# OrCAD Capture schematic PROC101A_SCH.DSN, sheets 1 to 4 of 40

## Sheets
1 04. BLOCK DIAGRAM_XDS110: title: BLOCK DIAGRAM_XDS110; rev: E2
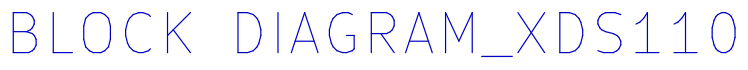
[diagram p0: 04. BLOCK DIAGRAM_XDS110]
2 16. CPSW RGMII_1 ETHERNET PHY: size C; title: CPSW RGMII_1 ETHERNET PHY
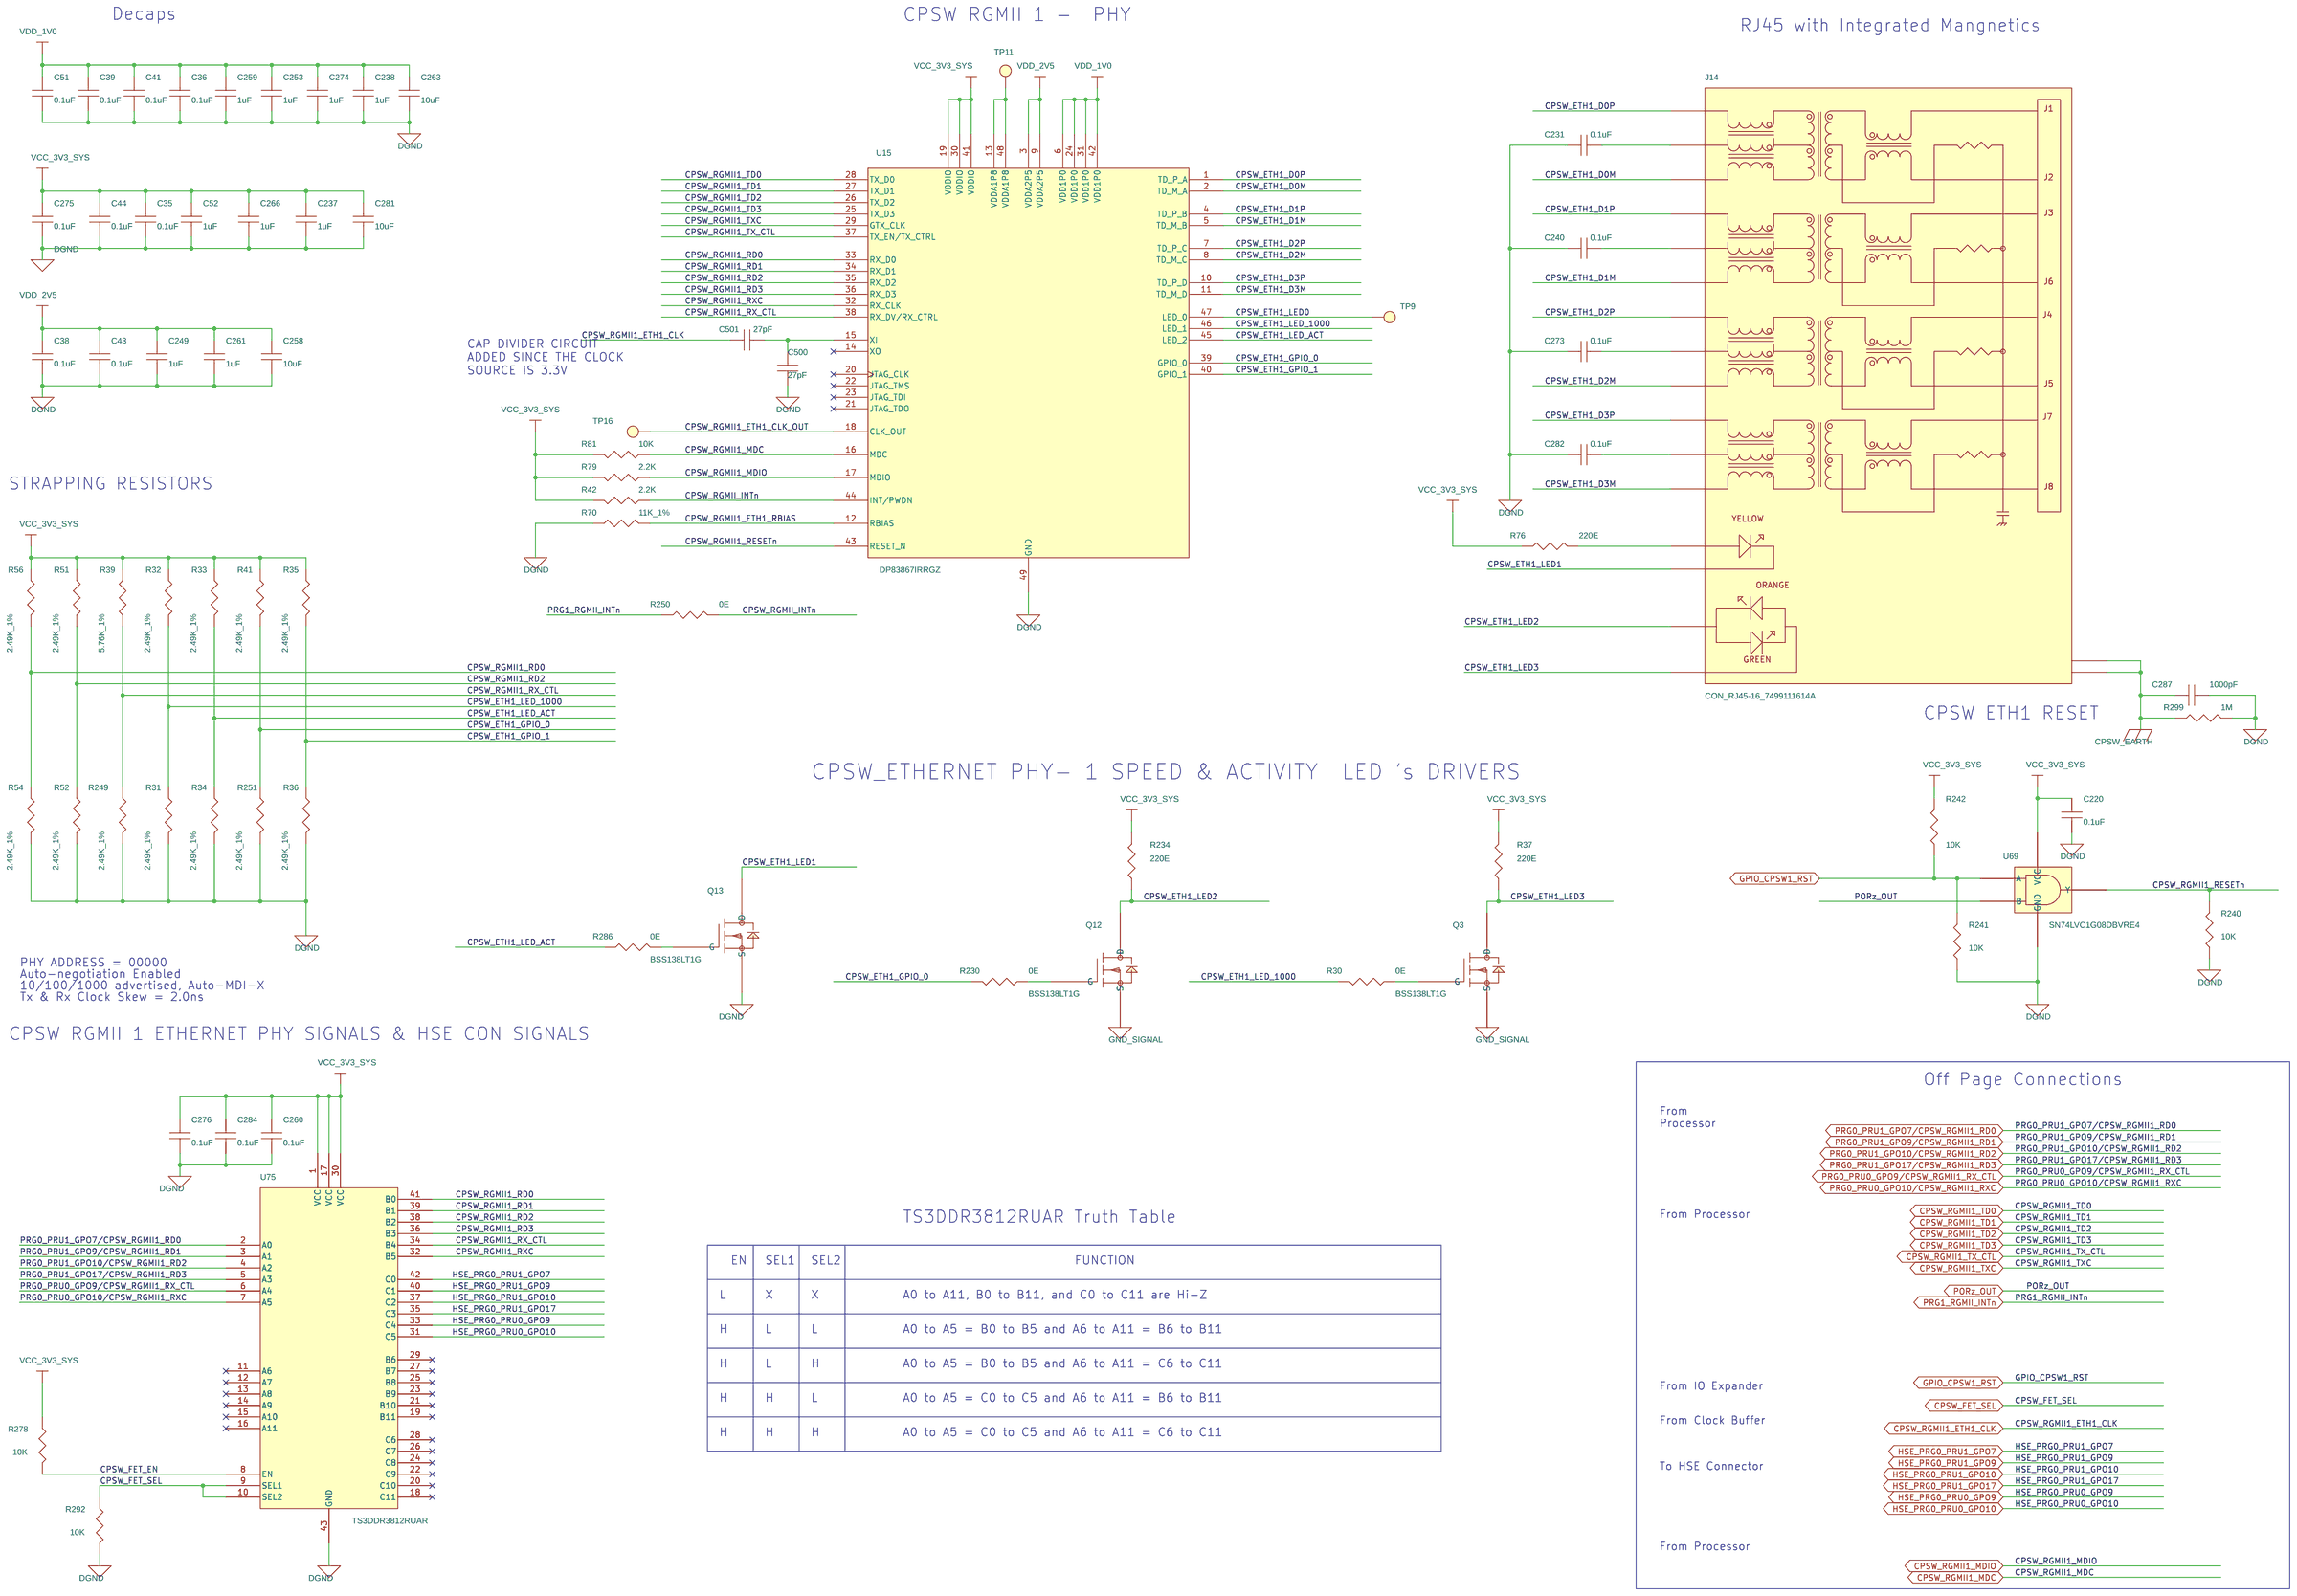
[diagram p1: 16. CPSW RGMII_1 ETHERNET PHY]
3 10.SOC POWER CAPS: size C; title: SOC POWER CAPS
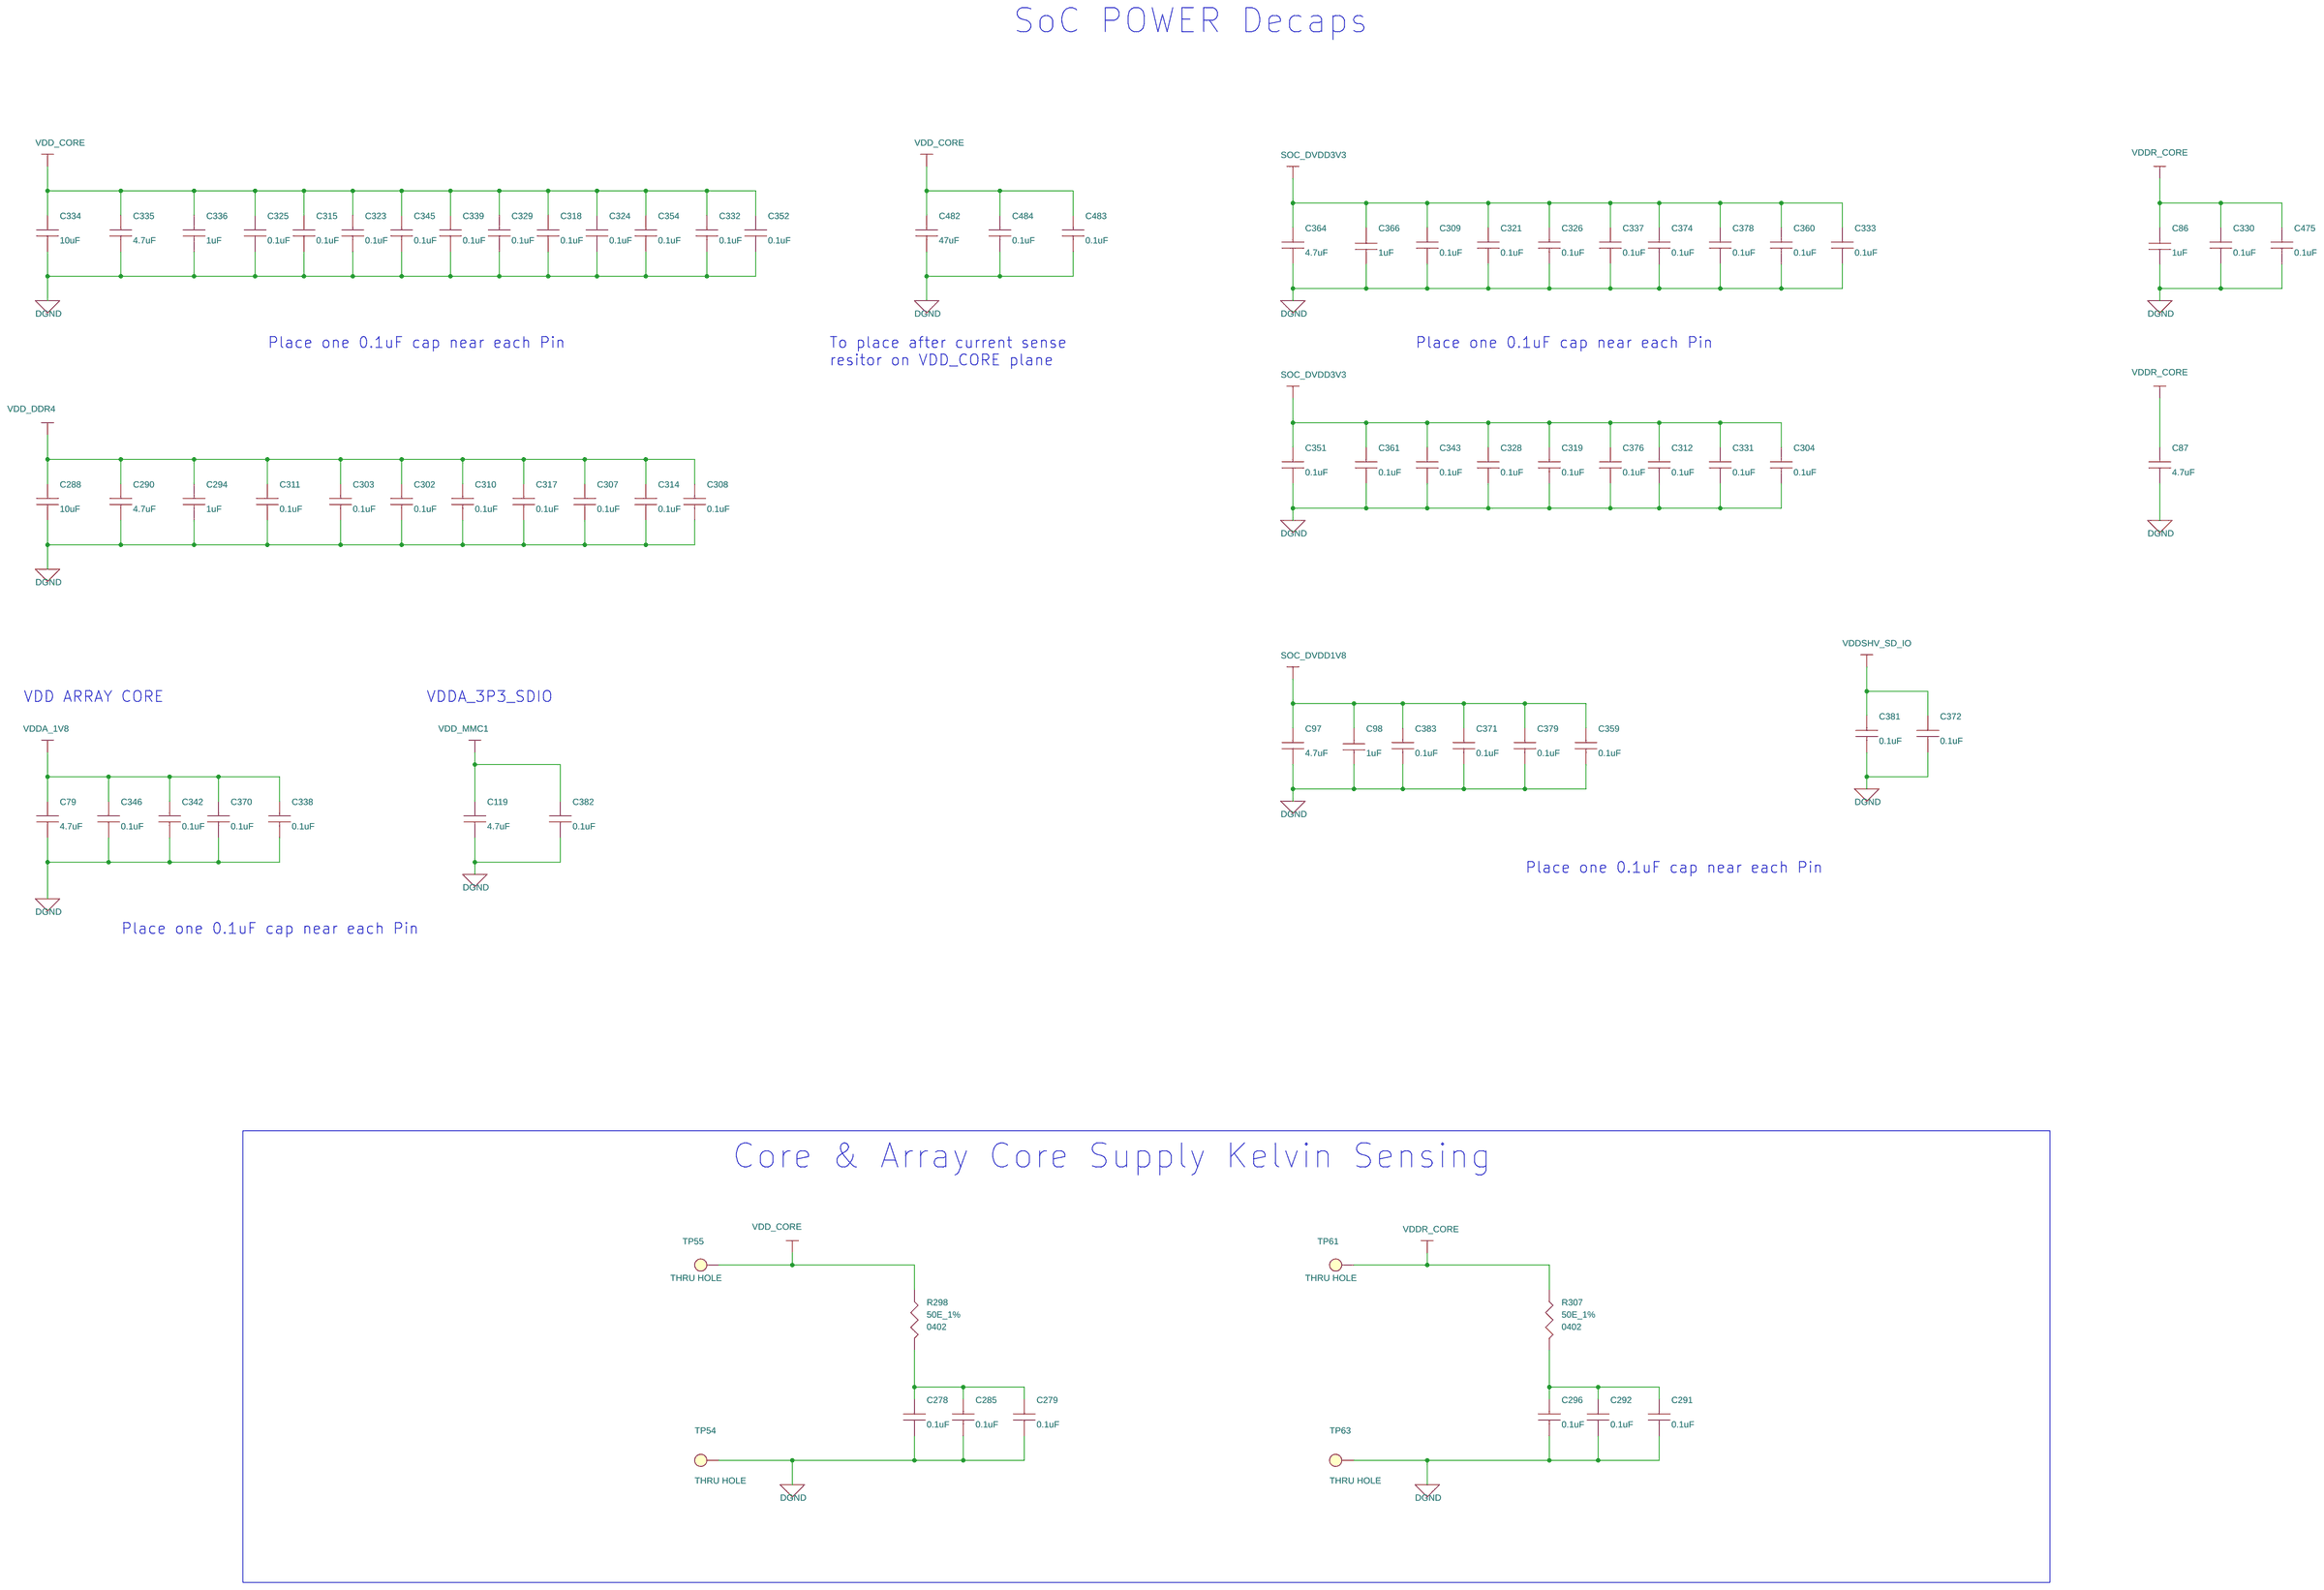
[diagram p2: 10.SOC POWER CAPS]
4 09.SOC POWER: size C; title: SOC POWER
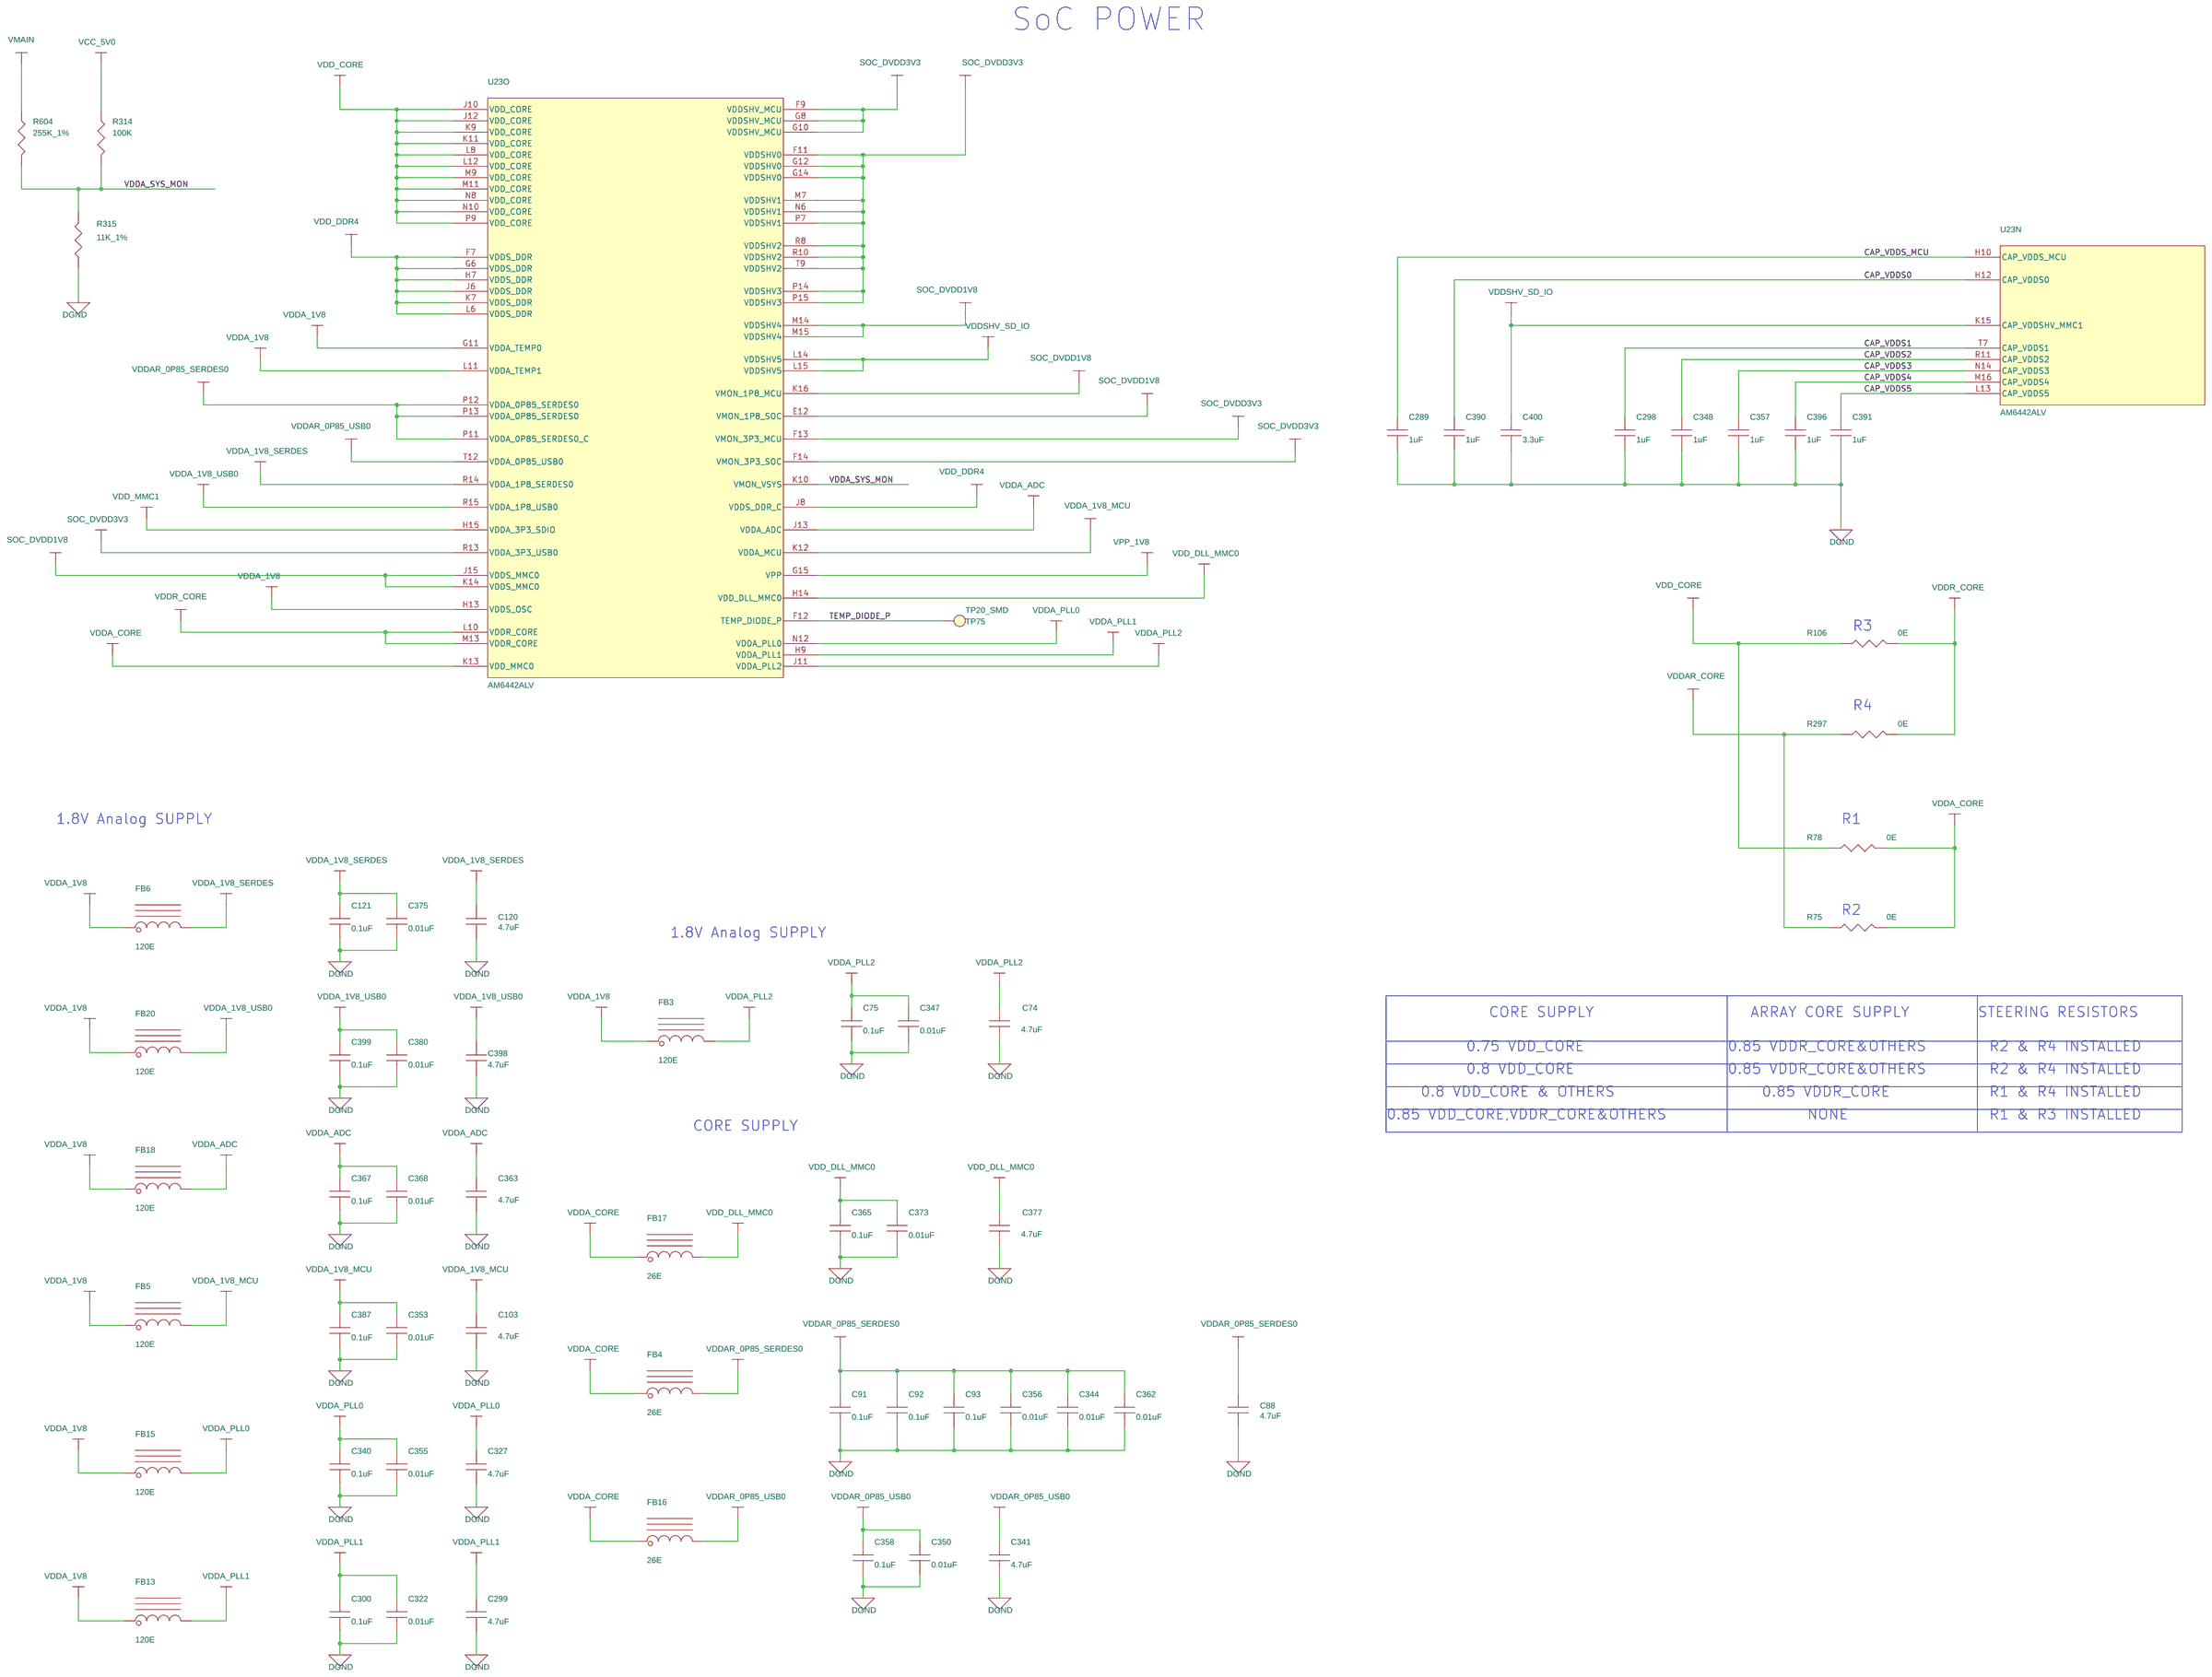
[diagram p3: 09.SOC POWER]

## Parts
sheet 09.SOC POWER
C74  4.7uF  [CAP0402_0-75]
C75  0.1uF  [CAP0201_0-5]
C88  4.7uF  [CAP0402_0-75]
C91  0.1uF  [CAP0201_0-5]
C92  0.1uF  [CAP0201_0-5]
C93  0.1uF  [CAP0201_0-5]
C103  4.7uF  [CAP0402_0-75]
C120  4.7uF  [CAP0402_0-75]
C121  0.1uF  [CAP0201_0-5]
C289  1uF  [CAP0201_0-5]
C298  1uF  [CAP0201_0-5]
C299  4.7uF  [CAP0402_0-75]
C300  0.1uF  [CAP0201_0-5]
C322  0.01uF  [CAP0201_0-5]
C327  4.7uF  [CAP0402_0-75]
C340  0.1uF  [CAP0201_0-5]
C341  4.7uF  [CAP0402_0-75]
C344  0.01uF  [CAP0201_0-5]
C347  0.01uF  [CAP0201_0-5]
C348  1uF  [CAP0201_0-5]
C350  0.01uF  [CAP0201_0-5]
C353  0.01uF  [CAP0201_0-5]
C355  0.01uF  [CAP0201_0-5]
C356  0.01uF  [CAP0201_0-5]
C357  1uF  [CAP0201_0-5]
C358  0.1uF  [CAP0201_0-5]
C362  0.01uF  [CAP0201_0-5]
C363  4.7uF  [CAP0402_0-75]
C365  0.1uF  [CAP0201_0-5]
C367  0.1uF  [CAP0201_0-5]
C368  0.01uF  [CAP0201_0-5]
C373  0.01uF  [CAP0201_0-5]
C375  0.01uF  [CAP0201_0-5]
C377  4.7uF  [CAP0402_0-75]
C380  0.01uF  [CAP0201_0-5]
C387  0.1uF  [CAP0201_0-5]
C390  1uF  [CAP0201_0-5]
C391  1uF  [CAP0201_0-5]
C396  1uF  [CAP0201_0-5]
C398  4.7uF  [CAP0402_0-75]
C399  0.1uF  [CAP0201_0-5]
C400  3.3uF  [CAP0603_1]
FB3  120E  [IND0603_1]
FB4  26E  [IND0603_1]
FB5  120E  [IND0603_1]
FB6  120E  [IND0603_1]
FB13  120E  [IND0603_1]
FB15  120E  [IND0603_1]
FB16  26E  [IND0603_1]
FB17  26E  [IND0603_1]
FB18  120E  [IND0603_1]
FB20  120E  [IND0603_1]
R75  0E  [RES1210_0-75]
R78  0E  [RES1210_0-75]
R106  0E  [RES1210_0-75]
R297  0E  [RES1210_0-75]
R314  100K  [RES0402_0-5]
R315  11K_1%  [RES0402_0-5]
R604  255K_1%  [RES0402_0-5]
TP75  TP20_SMD  [TP20_SMD]
sheet 10.SOC POWER CAPS
C79  4.7uF  [CAP0402_0-75]
C86  1uF  [CAP0402_0-75]
C87  4.7uF  [CAP0402_0-75]
C97  4.7uF  [CAP0402_0-75]
C98  1uF  [CAP0402_0-75]
C119  4.7uF  [CAP0402_0-75]
C278  0.1uF  [CAP0402_0-75]
C279  0.1uF  [CAP0402_0-75]
C285  0.1uF  [CAP0402_0-75]
C288  10uF  [CAP0402_0-75]
C290  4.7uF  [CAP0402_0-75]
C291  0.1uF  [CAP0402_0-75]
C292  0.1uF  [CAP0402_0-75]
C294  1uF  [CAP0402_0-75]
C296  0.1uF  [CAP0402_0-75]
C302  0.1uF  [CAP0201_0-5]
C303  0.1uF  [CAP0201_0-5]
C304  0.1uF  [CAP0201_0-5]
C307  0.1uF  [CAP0201_0-5]
C308  0.1uF  [CAP0201_0-5]
C309  0.1uF  [CAP0201_0-5]
C310  0.1uF  [CAP0201_0-5]
C311  0.1uF  [CAP0201_0-5]
C312  0.1uF  [CAP0201_0-5]
C314  0.1uF  [CAP0201_0-5]
C315  0.1uF  [CAP0201_0-5]
C317  0.1uF  [CAP0201_0-5]
C318  0.1uF  [CAP0201_0-5]
C319  0.1uF  [CAP0201_0-5]
C321  0.1uF  [CAP0201_0-5]
C323  0.1uF  [CAP0201_0-5]
C324  0.1uF  [CAP0201_0-5]
C325  0.1uF  [CAP0201_0-5]
C326  0.1uF  [CAP0201_0-5]
C328  0.1uF  [CAP0201_0-5]
C329  0.1uF  [CAP0201_0-5]
C330  0.1uF  [CAP0201_0-5]
C331  0.1uF  [CAP0201_0-5]
C332  0.1uF  [CAP0201_0-5]
C333  0.1uF  [CAP0201_0-5]
C334  10uF  [CAP0402_0-75]
C335  4.7uF  [CAP0402_0-75]
C336  1uF  [CAP0402_0-75]
C337  0.1uF  [CAP0201_0-5]
C338  0.1uF  [CAP0201_0-5]
C339  0.1uF  [CAP0201_0-5]
C342  0.1uF  [CAP0201_0-5]
C343  0.1uF  [CAP0201_0-5]
C345  0.1uF  [CAP0201_0-5]
C346  0.1uF  [CAP0201_0-5]
C351  0.1uF  [CAP0201_0-5]
C352  0.1uF  [CAP0201_0-5]
C354  0.1uF  [CAP0201_0-5]
C359  0.1uF  [CAP0201_0-5]
C360  0.1uF  [CAP0201_0-5]
C361  0.1uF  [CAP0201_0-5]
C364  4.7uF  [CAP0402_0-75]
C366  1uF  [CAP0402_0-75]
C370  0.1uF  [CAP0201_0-5]
C371  0.1uF  [CAP0201_0-5]
C372  0.1uF  [CAP0201_0-5]
C374  0.1uF  [CAP0201_0-5]
C376  0.1uF  [CAP0201_0-5]
C378  0.1uF  [CAP0201_0-5]
C379  0.1uF  [CAP0201_0-5]
C381  0.1uF  [CAP0201_0-5]
C382  0.1uF  [CAP0201_0-5]
C383  0.1uF  [CAP0201_0-5]
C475  0.1uF  [CAP0201_0-5]
C482  47uF  [CAP1206_2]
C483  0.1uF  [CAP0201_0-5]
C484  0.1uF  [CAP0201_0-5]
R298  50E_1%  [RES0402_0-75]
R307  50E_1%  [RES0402_0-75]
TP54  THRU HOLE  [TP_40X65]
TP55  THRU HOLE  [TP_40X65]
TP61  THRU HOLE  [TP_40X65]
TP63  THRU HOLE  [TP_40X65]
sheet 16. CPSW RGMII_1 ETHERNET PHY
C35  0.1uF  [CAP0402_0-75]
C36  0.1uF  [CAP0402_0-75]
C38  0.1uF  [CAP0402_0-75]
C39  0.1uF  [CAP0402_0-75]
C41  0.1uF  [CAP0402_0-75]
C43  0.1uF  [CAP0402_0-75]
C44  0.1uF  [CAP0402_0-75]
C51  0.1uF  [CAP0402_0-75]
C52  1uF  [CAP0402_0-75]
C220  0.1uF  [CAP0402_0-75]
C231  0.1uF  [CAP0201_0-5]
C237  1uF  [CAP0402_0-75]
C238  1uF  [CAP0402_0-75]
C240  0.1uF  [CAP0201_0-5]
C249  1uF  [CAP0402_0-75]
C253  1uF  [CAP0402_0-75]
C258  10uF  [CAP0402_0-75]
C259  1uF  [CAP0402_0-75]
C260  0.1uF  [CAP0402_0-75]
C261  1uF  [CAP0402_0-75]
C263  10uF  [CAP0402_0-75]
C266  1uF  [CAP0402_0-75]
C273  0.1uF  [CAP0201_0-5]
C274  1uF  [CAP0402_0-75]
C275  0.1uF  [CAP0402_0-75]
C276  0.1uF  [CAP0402_0-75]
C281  10uF  [CAP0402_0-75]
C282  0.1uF  [CAP0201_0-5]
C284  0.1uF  [CAP0402_0-75]
C287  1000pF  [CAP1206_1-75]
C500  27pF  [CAP0402_0-75]
C501  27pF  [CAP0402_0-75]
J14  CON_RJ45-16_7499111614A  [CON_RJ45-16_7499111614A_S_R_T_15-8]
Q3  BSS138LT1G  [SOT23-123_1-2]
Q12  BSS138LT1G  [SOT23-123_1-2]
Q13  BSS138LT1G  [SOT23-123_1-2]
R30  0E  [RES0402_0-5]
R31  2.49K_1%  [RES0402_0-5]
R32  2.49K_1%  [RES0402_0-5]
R33  2.49K_1%  [RES0402_0-5]
R34  2.49K_1%  [RES0402_0-5]
R35  2.49K_1%  [RES0402_0-5]
R36  2.49K_1%  [RES0402_0-5]
R37  220E  [RES0402_0-5]
R39  5.76K_1%  [RES0402_0-5]
R41  2.49K_1%  [RES0402_0-5]
R42  2.2K  [RES0402_0-5]
R51  2.49K_1%  [RES0402_0-5]
R52  2.49K_1%  [RES0402_0-5]
R54  2.49K_1%  [RES0402_0-5]
R56  2.49K_1%  [RES0402_0-5]
R70  11K_1%  [RES0402_0-5]
R76  220E  [RES0402_0-5]
R79  2.2K  [RES0402_0-5]
R81  10K  [RES0402_0-5]
R230  0E  [RES0402_0-5]
R234  220E  [RES0402_0-5]
R240  10K  [RES0402_0-5]
R241  10K  [RES0402_0-5]
R242  10K  [RES0402_0-5]
R249  2.49K_1%  [RES0402_0-5]
R250  0E  [RES0402_0-5]
R251  2.49K_1%  [RES0402_0-5]
R278  10K  [RES0402_0-5]
R286  0E  [RES0402_0-5]
R292  10K  [RES0402_0-5]
R299  1M  [RES0603_0-75]
TP9  TP20_SMD  [TP20_SMD]
TP11  TP20_SMD  [TP20_SMD]
TP16  TP20_SMD  [TP20_SMD]
U15  DP83867IRRGZ  [QFN48_19-68_280X280_1]
U69  SN74LVC1G08DBVRE4  [SOT23-5]
U75  TS3DDR3812RUAR  [TQFN42_19-68_140X360_0-8]
sheet 28.GPMC & FSI CONNECTOR
U23  AM6442ALV  [FCBGA441_31-49_680X680_2-6]  (sections A,B,C,D,E,F,G,H,I,J,K,L,M,N,O,P)

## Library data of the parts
C74 C79 C87 C88 C97 C103 C119 C120 C290 C299 C327 C335 C341 C363 C364 C377 C398 = CAP: CAP CERAMIC 4.7uF 10V 20% X5R 0402; Chkd/date: MANIRAJA/230118; Crtd /date: MANIRAJA/230118; Custom_Duty: 15%; Customs_HS_Code: 85322990; Distributor_name: DIGIKEY; Distributor_part_number: 478-10791-1-ND; Footprint Path: Y:\MIS_DATABASE\Library\ALTIUM_TOOL\PCB_FOOTPRINTS\Altium_Footprint_Lib.PcbLib; Height: 0.71MM; Library Path: Y:\MIS_DATABASE\Library\ALTIUM_TOOL\SCHEMATICS_PARTS\MS_DISCRETE_Library.schlib; Mfr_name: AVX CORPORATION; Mfr_part_number: 0402ZD475MAT2A; Mistral Part No: 120012060002-R; Package: 0402; Part_type: CAPACITORS\CERAMIC; Project: TI_MAXIE_CPB; RoHS: RoHS; Temperature: -55°C+85°C; Tolerance: 20%; Voltage: 10V; Wattage: NA; Weight: 0.65mg; Datasheet: Y:\MIS_DATABASE\DATASHEETS\CAPACITORS\AVX_MLC.PDF
C75 C91-C93 C121 C231 C240 C273 C282 C300 C302-C304 C307-C312 C314 C315 C317-C319 C321 C323-C326 C328-C333 C337-C340 C342 C343 C345 C346 C351 C352 C354 C358-C361 C365 C367 C370-C372 C374 C376 C378 C379 C381-C383 C387 C399 C475 C483 C484 = CAP: CAP CERAMIC 0.1uF 16V 10% X5R 0201; Chkd/date: MANIRAJA/120218; Crtd /date: MANIRAJA/120218; Custom_Duty: 15%; Customs_HS_Code: 85322990; Distributor_name: DIGIKEY; Distributor_part_number: 490-16742-1-ND; Footprint Path: Y:\MIS_DATABASE\Library\ALTIUM_TOOL\PCB_FOOTPRINTS\Altium_Footprint_Lib.PcbLib; Height: 0.33MM; Library Path: Y:\MIS_DATABASE\Library\ALTIUM_TOOL\SCHEMATICS_PARTS\MS_DISCRETE_Library.schlib; Mfr_name: MURATA; Mfr_part_number: GRM033R61C104KE84J; Mistral Part No: 120009030072-R; Package: 0201; Part_type: CAPACITORS\CERAMIC; Project: TI_MAXIE_CPB; RoHS: RoHS; Temperature: -55°C+85°C; Tolerance: 10%; Voltage: 16V; Wattage: NA; Weight: 0.33mg; Datasheet: Y:\MIS_DATABASE\DATASHEETS\CAPACITORS\GRM033R61C104KE84.PDF
C289 C298 C348 C357 C390 C391 C396 = CAP: CAP CERAMIC 1uF 6.3V 20% X5R 0201; Chkd/date: MANIRAJA/091219; Crtd /date: ALVY/091219; Custom_Duty: 15%; Customs_HS_Code: 85322990; Distributor_name: DIGIKEY; Distributor_part_number: 490-7229-1-ND; Footprint Path: Y:\MIS_DATABASE\Library\ALTIUM_TOOL\PCB_FOOTPRINTS\Altium_Footprint_Lib.PcbLib; Height: 0.35MM; Library Path: Y:\MIS_DATABASE\Library\ALTIUM_TOOL\SCHEMATICS_PARTS\MS_DISCRETE_Library.schlib; Mfr_name: MURATA; Mfr_part_number: GRM033R60J105MEA2D; Mistral Part No: 120012060001-R; Package: 0201; Part_type: CAPACITORS\CERAMIC; Project: MYTHIC_X16_BRD; RoHS: RoHS; Temperature: -55°C+85°C; Tolerance: 20%; Voltage: 6.3V; Wattage: NA; Weight: 7mg; Datasheet: Y:\MIS_DATABASE\DATASHEETS\CAPACITORS\GRM033R60J105MEA2.PDF
C322 C344 C347 C350 C353 C355 C356 C362 C368 C373 C375 C380 = CAP: CAP CERAMIC 0.01uF 25V 10% X5R 0201; Chkd/date: MANIRAJA/230118; Crtd /date: MANIRAJA/230118; Custom_Duty: 15%; Customs_HS_Code: 85322990; Distributor_name: DIGIKEY; Distributor_part_number: GRM033R61E103KA12J-ND; Footprint Path: Y:\MIS_DATABASE\Library\ALTIUM_TOOL\PCB_FOOTPRINTS\Altium_Footprint_Lib.PcbLib; Height: 0.33MM; Library Path: Y:\MIS_DATABASE\Library\ALTIUM_TOOL\SCHEMATICS_PARTS\MS_DISCRETE_Library.schlib; Mfr_name: MURATA; Mfr_part_number: GRM033R61E103KA12J; Mistral Part No: 120018010007-R; Package: 0201; Part_type: CAPACITORS\CERAMIC; Project: TI_MAXIE_CPB; RoHS: RoHS; Temperature: -55°C+85°C; Tolerance: 10%; Voltage: 25V; Wattage: NA; Weight: 0.33mg; Datasheet: Y:\MIS_DATABASE\DATASHEETS\CAPACITORS\GRM033R61E103KA12.PDF
C400 = CAP: CAP CERAMIC 3.3uF 6.3V 20% X5R AUTO 0603; Chkd/date: ALVY/110221; Crtd /date: MANIRAJA/110221; Custom_Duty: 15%; Customs_HS_Code: 85322990; Distributor_name: DIGIKEY; Distributor_part_number: 445-12524-1-ND; Footprint Path: Y:\MIS_DATABASE\Library\ALTIUM_TOOL\PCB_FOOTPRINTS\Altium_Footprint_Lib.PcbLib; Height: 0.90MM; Library Path: Y:\MIS_DATABASE\Library\ALTIUM_TOOL\SCHEMATICS_PARTS\MS_DISCRETE_Library.schlib; Mfr_name: TDK; Mfr_part_number: CGA3E3X5R0J335M080AB; Mistral Part No: 120021020026-R; Package: 0603; Part_type: CAPACITORS\CERAMIC; Project: TI_AM243x LP EVM; RoHS: RoHS; Temperature: -55°C+85°C; Tolerance: 20%; Voltage: 6.3V; Wattage: NA; Weight: 6.3mg; Datasheet: Y:\MIS_DATABASE\DATASHEETS\CAPACITORS\CGA3E3X5R0J335M080AB.PDF
FB3 FB5 FB6 FB13 FB15 FB18 FB20 = INDUCTOR_FERRITE: IND FERRITE BEAD CHIP 120E 2A 0603; Chkd/date: MANIRAJA/180820; Crtd /date: ALVY/180820; Custom_Duty: 24%; Customs_HS_Code: 85437099; Distributor_name: DIGIKEY; Distributor_part_number: 732-782631141CT-ND; Footprint Path: Y:\MIS_DATABASE\Library\ALTIUM_TOOL\PCB_FOOTPRINTS\Altium_Footprint_Lib.PcbLib; Height: 1.00MM; Library Path: Y:\MIS_DATABASE\Library\ALTIUM_TOOL\SCHEMATICS_PARTS\MS_FILTER_Library.schlib; Mfr_name: WURTH ELECTRONICS; Mfr_part_number: 782631141; Mistral Part No: 130020080015-R; Package: 0603; Part_type: INDUCTOR; Project: AM64x_EVM_BRD; RoHS: RoHS; Temperature: -55°C+125°C; Tolerance: 25%; Voltage: NA; Wattage: NA; Weight: NA; Datasheet: Y:\MIS_DATABASE\DATASHEETS\DISCRETES\INDUCTORS\782631141.PDF
FB4 FB16 FB17 = INDUCTOR_FERRITE: IND FERRITE BEAD CHIP 26E 6.5A 0603; Chkd/date: MANIRAJA/180820; Crtd /date: ALVY/180820; Custom_Duty: 24%; Customs_HS_Code: 85437099; Distributor_name: DIGIKEY; Distributor_part_number: 732-6117-1-ND; Footprint Path: Y:\MIS_DATABASE\Library\ALTIUM_TOOL\PCB_FOOTPRINTS\Altium_Footprint_Lib.PcbLib; Height: 1.00MM; Library Path: Y:\MIS_DATABASE\Library\ALTIUM_TOOL\SCHEMATICS_PARTS\MS_FILTER_Library.schlib; Mfr_name: WURTH ELECTRONICS; Mfr_part_number: 74279228260; Mistral Part No: 130020080017-R; Package: 0603; Part_type: INDUCTOR; Project: AM64x_EVM_BRD; RoHS: RoHS; Temperature: -55°C+125°C; Tolerance: 25%; Voltage: NA; Wattage: NA; Weight: 2mg; Datasheet: Y:\MIS_DATABASE\DATASHEETS\DISCRETES\INDUCTORS\74279228260.PDF
R75 R78 R106 R297 = RESISTOR: RES 0E 1/2W 5% 1210; Chkd/date: VASANTHA/281216; Crtd /date: USMAN/080109; Custom_Duty: 15%; Customs_HS_Code: 85332119; Distributor_name: MOUSER; Distributor_part_number: 603-RC1210JR-070RL; Footprint Path: Y:\MIS_DATABASE\Library\ALTIUM_TOOL\PCB_FOOTPRINTS\Altium_Footprint_Lib.PcbLib; Height: 0.65MM; Library Path: Y:\MIS_DATABASE\Library\ALTIUM_TOOL\SCHEMATICS_PARTS\MS_DISCRETE_Library.schlib; Mfr_name: YAGEO AMERICA; Mfr_part_number: RC1210JR-070RL; Mistral Part No: 110009030080-R; Package: 1210; Part_type: RESISTORS\FIXED; Project: OMAP_EVM; RoHS: RoHS; Temperature: -55°C+155°C; Tolerance: 5%; Voltage: NA; Wattage: 1/2W; Weight: 10mg; Datasheet: Y:\MIS_DATABASE\DATASHEETS\RESISTORS\RCXXXXL-SER_MAR18.PDF
R314 = RESISTOR: RES 100K 1/16W 5% 0402; Chkd/date: VASANTHA/061216; Crtd /date: BAVISH/010611; Custom_Duty: 15%; Customs_HS_Code: 85332119; Distributor_name: DIGIKEY; Distributor_part_number: 541-100KJCT-ND; Footprint Path: Y:\MIS_DATABASE\Library\ALTIUM_TOOL\PCB_FOOTPRINTS\Altium_Footprint_Lib.PcbLib; Height: 0.40MM; Library Path: Y:\MIS_DATABASE\Library\ALTIUM_TOOL\SCHEMATICS_PARTS\MS_DISCRETE_Library.schlib; Mfr_name: VISHAY; Mfr_part_number: CRCW0402100KJNED; Mistral Part No: 110011060002-R; Package: 0402; Part_type: RESISTORS\FIXED; Project: AM4515_EVM_LCD; RoHS: RoHS; Temperature: -55°C+155°C; Tolerance: 5%; Voltage: NA; Wattage: 1/16W; Weight: 0.65mg; Datasheet: Y:\MIS_DATABASE\DATASHEETS\RESISTORS\CRCW0603.PDF
R70 R315 = RESISTOR: RES 11K 1/16W 1% 0402; Chkd/date: VASANTHA/251115; Crtd /date: VASANTHA/251115; Custom_Duty: 15%; Customs_HS_Code: 85332119; Distributor_name: DIGIKEY; Distributor_part_number: 311-11.0KLRCT-ND; Footprint Path: Y:\MIS_DATABASE\Library\ALTIUM_TOOL\PCB_FOOTPRINTS\Altium_Footprint_Lib.PcbLib; Height: 0.40MM; Library Path: Y:\MIS_DATABASE\Library\ALTIUM_TOOL\SCHEMATICS_PARTS\MS_DISCRETE_Library.schlib; Mfr_name: YAGEO AMERICA; Mfr_part_number: RC0402FR-0711KL; Mistral Part No: 110015110012-R; Package: 0402; Part_type: RESISTORS\FIXED; Project: TI_VLAN_SWITCH; RoHS: RoHS; Temperature: -55°C+155°C; Tolerance: 1%; Voltage: NA; Wattage: 1/16W; Weight: 0.65mg; Datasheet: Y:\MIS_DATABASE\DATASHEETS\RESISTORS\RCXXXXL-SER_MAR18.PDF
R604 = RESISTOR: RES 255K 1/10W 1% 0402; Chkd/date: MANIRAJA/160218; Crtd /date: MANIRAJA/160218; Custom_Duty: 15%; Customs_HS_Code: 85332119; Distributor_name: DIGIKEY; Distributor_part_number: P255KLCT-ND; Footprint Path: Y:\MIS_DATABASE\Library\ALTIUM_TOOL\PCB_FOOTPRINTS\Altium_Footprint_Lib.PcbLib; Height: 0.40MM; Library Path: Y:\MIS_DATABASE\Library\ALTIUM_TOOL\SCHEMATICS_PARTS\MS_DISCRETE_Library.schlib; Mfr_name: PANASONIC-ECG; Mfr_part_number: ERJ-2RKF2553X; Mistral Part No: 110018020016-R; Package: 0402; Part_type: RESISTORS\FIXED; Project: NPOL_SAR_ADC; RoHS: RoHS; Temperature: -55°C+155°C; Tolerance: 1%; Voltage: NA; Wattage: 1/10W; Weight: 0.8mg; Datasheet: Y:\MIS_DATABASE\DATASHEETS\RESISTORS\PAN-ERJSER_NOV17.PDF
TP9 TP11 TP16 TP75 = TESTPOINT: TESTPOINT CIR 20 SMD; Chkd/date: SHREESHAIL/171006; Crtd /date: MAZHAR/171006; Custom_Duty: NA; Customs_HS_Code: NA; Distributor_name: NA; Distributor_part_number: NA; Footprint Path: Y:\MIS_DATABASE\Library\ALTIUM_TOOL\PCB_FOOTPRINTS\Altium_Footprint_Lib.PcbLib; Height: NA; Library Path: Y:\MIS_DATABASE\Library\ALTIUM_TOOL\SCHEMATICS_PARTS\MS_DISCRETE_Library.schlib; MECHANICAL 3D STEP FILE: NA; Mfr_name: LOCAL; Mistral Part No: NA; Package: SMD; Project: BT MODULE_CSRBC04; RoHS: NA; Temperature: NA; Tolerance: NA; Voltage: NA; Wattage: NA; Weight: NA; Datasheet: NA
C52 C86 C98 C237 C238 C249 C253 C259 C261 C266 C274 C294 C336 C366 = CAP: CAP CERAMIC 1uF 10V 20% X5R 0402; Chkd/date: MANIRAJA/210820; Crtd /date: ALVY/190820; Custom_Duty: 15%; Customs_HS_Code: 85322990; Distributor_name: DIGIKEY; Distributor_part_number: 732-7489-1-ND; Footprint Path: Y:\MIS_DATABASE\Library\ALTIUM_TOOL\PCB_FOOTPRINTS\Altium_Footprint_Lib.PcbLib; Height: 0.55MM; Library Path: Y:\MIS_DATABASE\Library\ALTIUM_TOOL\SCHEMATICS_PARTS\MS_DISCRETE_Library.schlib; Mfr_name: WURTH ELECTRONICS; Mfr_part_number: 885012105012; Mistral Part No: 120020080009-R; Package: 0402; Part_type: CAPACITORS\CERAMIC; Project: AM64x_EVM_BRD; RoHS: RoHS; Temperature: -55°C+85°C; Tolerance: 20%; Voltage: 10V; Wattage: NA; Weight: 0.65mg; Datasheet: Y:\MIS_DATABASE\DATASHEETS\CAPACITORS\885012105012.PDF
C35 C36 C38 C39 C41 C43 C44 C51 C220 C260 C275 C276 C278 C279 C284 C285 C291 C292 C296 = CAP: CAP CERAMIC 0.1uF 25V 20% X5R 0402; Alt_Mfr_name: YAGEO AMERICA; Alt_Mfr_part_number: CC0402KRX5R8BB104; Chkd/date: MANIRAJA/170820; Crtd /date: ALVY/170820; Custom_Duty: 15%; Customs_HS_Code: 85322990; Distributor_name: DIGIKEY; Distributor_part_number: 732-7495-1-ND; Footprint Path: Y:\MIS_DATABASE\Library\ALTIUM_TOOL\PCB_FOOTPRINTS\Altium_Footprint_Lib.PcbLib; Height: 0.55MM; Library Path: Y:\MIS_DATABASE\Library\ALTIUM_TOOL\SCHEMATICS_PARTS\MS_DISCRETE_Library.schlib; Mfr_name: WURTH ELECTRONICS; Mfr_part_number: 885012105018; Mistral Part No: 120020080003-R; Package: 0402; Part_type: CAPACITORS\CERAMIC; Project: AM64x_EVM_BRD; RoHS: RoHS; Temperature: -55°C+85°C; Tolerance: 20%; Voltage: 25V; Wattage: NA; Weight: 0.65mg; Datasheet: Y:\MIS_DATABASE\DATASHEETS\CAPACITORS\885012105018.PDF
C258 C263 C281 C288 C334 = CAP: CAP CERAMIC 10uF 10V 20% X5R 0402; Chkd/date: MANIRAJA/300520; Crtd /date: ALVY/260520; Custom_Duty: 15%; Customs_HS_Code: 85322990; Distributor_name: DIGIKEY; Distributor_part_number: 490-GRM155R61A106ME11DTR-ND; Footprint Path: Y:\MIS_DATABASE\Library\ALTIUM_TOOL\PCB_FOOTPRINTS\Altium_Footprint_Lib.PcbLib; Height: 0.55MM; Library Path: Y:\MIS_DATABASE\Library\ALTIUM_TOOL\SCHEMATICS_PARTS\MS_DISCRETE_Library.schlib; Mfr_name: MURATA; Mfr_part_number: GRM155R61A106ME11D; Mistral Part No: 120013110019-R; Package: 0402; Part_type: CAPACITORS\CERAMIC; Project: QCS610_NANOSOM; RoHS: RoHS; Temperature: -55°C+85°C; Tolerance: 20%; Voltage: 10V; Wattage: NA; Weight: 3.1mg; Datasheet: Y:\MIS_DATABASE\DATASHEETS\CAPACITORS\MURATA-GXX-SER_NOV17.PDF
C482 = CAP: CAP CERAMIC 47uF 25V 20% X5R 1206; Chkd/date: MANIRAJA/230118; Crtd /date: MANIRAJA/230118; Custom_Duty: 15%; Customs_HS_Code: 85322990; Distributor_name: DIGIKEY; Distributor_part_number: 490-16268-1-ND; Footprint Path: Y:\MIS_DATABASE\Library\ALTIUM_TOOL\PCB_FOOTPRINTS\Altium_Footprint_Lib.PcbLib; Height: 1.80MM; Library Path: Y:\MIS_DATABASE\Library\ALTIUM_TOOL\SCHEMATICS_PARTS\MS_DISCRETE_Library.schlib; Mfr_name: MURATA; Mfr_part_number: GRM31CR61E476ME44L; Mistral Part No: 120013050002-R; Package: 1206; Part_type: CAPACITORS\CERAMIC; Project: TI_MAXIE_CPB; RoHS: RoHS; Temperature: -55°C+85°C; Tolerance: 20%; Voltage: 25V; Wattage: NA; Weight: 40mg; Datasheet: Y:\MIS_DATABASE\DATASHEETS\CAPACITORS\MURATA-GXX-SER_NOV17.PDF
R298 R307 = RESISTOR: RES 50E 1/8W 1% 0402; Chkd/date: MANIRAJA/160218; Crtd /date: ALVY/140218; Custom_Duty: 15%; Customs_HS_Code: 85332119; Distributor_name: DIGIKEY; Distributor_part_number: 1284-1326-1-ND; Footprint Path: Y:\MIS_DATABASE\Library\ALTIUM_TOOL\PCB_FOOTPRINTS\Altium_Footprint_Lib.PcbLib; Height: 0.60MM; Library Path: Y:\MIS_DATABASE\Library\ALTIUM_TOOL\SCHEMATICS_PARTS\MS_DISCRETE_Library.schlib; Mfr_name: ATC; Mfr_part_number: 504L50R0FTNCFT; Mistral Part No: 110018020017-R; Package: 0402; Part_type: RESISTORS\FIXED; Project: TI_SVB_MAXWELL_SPM; RoHS: RoHS; Temperature: -40°C+125°C; Tolerance: 1%; Voltage: NA; Wattage: 1/8W; Weight: 0.65mg; Datasheet: Y:\MIS_DATABASE\DATASHEETS\RESISTORS\ATC504L-SERIES.PDF
TP54 TP55 TP61 TP63 = TESTPOINT: TESTPOINT 1.0MM DRILL PTH; Chkd/date: MAZHAR/271211; Crtd /date: SHREESHAIL/041005; Distributor_name: NA; Distributor_part_number: NA; Height: NA; Mfr_name: LOCAL; Mistral Part No: 130009030938; Package: THRU-HOLE; Project: HSE; Datasheet: NA
C287 = CAP: CAP CERAMIC 1000pF 2KV 10% X7R 1206; Chkd/date: SHREESHAIL/291106; Crtd /date: MAZHAR/281106; Custom_Duty: 15%; Customs_HS_Code: 85322990; Distributor_name: DIGIKEY; Distributor_part_number: 478-2956-1-ND; Footprint Path: Y:\MIS_DATABASE\Library\ALTIUM_TOOL\PCB_FOOTPRINTS\Altium_Footprint_Lib.PcbLib; Height: 1.52MM; Library Path: Y:\MIS_DATABASE\Library\ALTIUM_TOOL\SCHEMATICS_PARTS\MS_DISCRETE_Library.schlib; Mfr_name: AVX CORPORATION; Mfr_part_number: 1206GC102KAT1A; Mistral Part No: 120015080006-R; Package: 1206; Part_type: CAPACITORS\CERAMIC; Project: ADR1B; RoHS: RoHS; Temperature: -55°C+125°C; Tolerance: 10%; Voltage: 2KV; Wattage: NA; Weight: 16.2mg; Datasheet: Y:\MIS_DATABASE\DATASHEETS\CAPACITORS\AVX_HV-MLC.PDF
C500 C501 = CAP: CAP CERAMIC 27pF 16V 5% C0G(NP0) 0402; Chkd/date: ALVY/100221; Crtd /date: MANIRAJA/100221; Custom_Duty: 15%; Customs_HS_Code: 85322990; Distributor_name: DIGIKEY; Distributor_part_number: 478-0402YA270JAT2ACT-ND; Footprint Path: Y:\MIS_DATABASE\Library\ALTIUM_TOOL\PCB_FOOTPRINTS\Altium_Footprint_Lib.PcbLib; Height: 0.56MM; Library Path: Y:\MIS_DATABASE\Library\ALTIUM_TOOL\SCHEMATICS_PARTS\MS_DISCRETE_Library.schlib; Mfr_name: AVX CORPORATION; Mfr_part_number: 0402YA270JAT2A; Mistral Part No: 120021020020-R; Package: 0402; Part_type: CAPACITORS\CERAMIC; Project: TI_AM64x_EVM; RoHS: RoHS; Temperature: -55°C+125°C; Tolerance: 5%; Voltage: 16V; Wattage: NA; Weight: 1.5mg; Datasheet: Y:\MIS_DATABASE\DATASHEETS\CAPACITORS\AVX_MLC.PDF
J14 = CON_RJ45-16_7499111614A: CON JACK RJ-45 16POS FEMALE RT TH; Chkd/date: MANIRAJA/060519; Crtd /date: ALVY/060519; Custom_Duty: 24%; Customs_HS_Code: 85369090; Distributor_name: DIGIKEY; Distributor_part_number: 732-12036-5-ND; Footprint Path: Y:\MIS_DATABASE\Library\ALTIUM_TOOL\PCB_FOOTPRINTS\Altium_Footprint_Lib.PcbLib; Height: 15.79MM; Library Path: Y:\MIS_DATABASE\Library\ALTIUM_TOOL\SCHEMATICS_PARTS\MS_CONNECTOR_Library.schlib; Mfr_name: WURTH ELECTRONICS; Mfr_part_number: 7499111614A; Mistral Part No: 150019050003-R; Package: THRU-HOLE; Part_type: CONNECTOR\JACK; Project: J7ES_ENET_DP83869HM_EXP; RoHS: RoHS; Temperature: 0°C+70°C; Tolerance: NA; Voltage: NA; Wattage: NA; Weight: 9360mg; Datasheet: Y:\MIS_DATABASE\DATASHEETS\CONNECTORS\7499111614A.PDF
Q3 Q12 Q13 = MOSFET_BSS138LT1G: IC MOSFET N-CHANNEL 50V 200mA SOT23-3; Chkd/date: MANIRAJA/250219; Crtd /date: JEBRAN/060416; Custom_Duty: 15%; Customs_HS_Code: 85423100; Distributor_name: DIGIKEY; Distributor_part_number: BSS138LT1GOSCT-ND; Footprint Path: Y:\MIS_DATABASE\Library\ALTIUM_TOOL\PCB_FOOTPRINTS\Altium_Footprint_Lib.PcbLib; Height: 1.11MM; Library Path: Y:\MIS_DATABASE\Library\ALTIUM_TOOL\SCHEMATICS_PARTS\MS_MOSFET_Library.schlib; Library Ref: MOSFET_BSS138W; Mfr_name: ON SEMICONDUCTOR; Mistral Part No: 142016040001-R; Package: SOT23-3; Part_type: ICS\POWER\MOSFET; Project: LRDE_ABCM; RoHS: RoHS; Temperature: -55°C+150°C; Tolerance: NA; Voltage: NA; Wattage: NA; Weight: 8mg; Datasheet: Y:\MIS_DATABASE\DATASHEETS\DISCRETES\TRANSISTORS_FETS\BSS138LT1G.PDF
R30 R230 R250 R286 = RESISTOR: RES 0E 1/16W JUMPER 0402; Chkd/date: VASANTHA/201216; Crtd /date: MUDDU/190810; Custom_Duty: 15%; Customs_HS_Code: 85332119; Distributor_name: DIGIKEY; Distributor_part_number: 541-0.0JCT-ND; Footprint Path: Y:\MIS_DATABASE\Library\ALTIUM_TOOL\PCB_FOOTPRINTS\Altium_Footprint_Lib.PcbLib; Height: 0.40MM; Library Path: Y:\MIS_DATABASE\Library\ALTIUM_TOOL\SCHEMATICS_PARTS\MS_DISCRETE_Library.schlib; Mfr_name: VISHAY; Mfr_part_number: CRCW04020000Z0ED; Mistral Part No: 110010080019-R; Package: 0402; Part_type: RESISTORS\FIXED; Project: PB_BUGBASE; RoHS: RoHS; Temperature: -55°C+155°C; Tolerance: NA; Voltage: NA; Wattage: 1/16W; Weight: 0.65mg; Datasheet: Y:\MIS_DATABASE\DATASHEETS\RESISTORS\CRCW0603.PDF
R31-R36 R41 R51 R52 R54 R56 R249 R251 = RESISTOR: RES 2.49K 1/16W 1% 0402; Chkd/date: VASANTHA/270516; Crtd /date: VASANTHA/270516; Custom_Duty: 15%; Customs_HS_Code: 85332119; Distributor_name: DIGIKEY; Distributor_part_number: 311-2.49KLRCT-ND; Footprint Path: Y:\MIS_DATABASE\Library\ALTIUM_TOOL\PCB_FOOTPRINTS\Altium_Footprint_Lib.PcbLib; Height: 0.40MM; Library Path: Y:\MIS_DATABASE\Library\ALTIUM_TOOL\SCHEMATICS_PARTS\MS_DISCRETE_Library.schlib; Mfr_name: YAGEO AMERICA; Mfr_part_number: RC0402FR-072K49L; Mistral Part No: 110016050020-R; Package: 0402; Part_type: RESISTORS\FIXED; Project: TMDXCSKCC; RoHS: RoHS; Temperature: -55°C+155°C; Tolerance: 1%; Voltage: NA; Wattage: 1/16W; Weight: 0.65mg; Datasheet: Y:\MIS_DATABASE\DATASHEETS\RESISTORS\RCXXXXL-SER_MAR18.PDF
R37 R76 R234 = RESISTOR: RES 220E 1/10W 5% 0402; Chkd/date: VASANTHA/291216; Crtd /date: GEETHA/260406; Custom_Duty: 15%; Customs_HS_Code: 85332119; Distributor_name: DIGIKEY; Distributor_part_number: P220JCT-ND; Footprint Path: Y:\MIS_DATABASE\Library\ALTIUM_TOOL\PCB_FOOTPRINTS\Altium_Footprint_Lib.PcbLib; Height: 0.40MM; Library Path: Y:\MIS_DATABASE\Library\ALTIUM_TOOL\SCHEMATICS_PARTS\MS_DISCRETE_Library.schlib; Mfr_name: PANASONIC-ECG; Mfr_part_number: ERJ-2GEJ221X; Mistral Part No: 110009030506-R; Package: 0402; Part_type: RESISTORS\FIXED; Project: RED EYE; RoHS: RoHS; Temperature: -55°C+155°C; Tolerance: 5%; Voltage: NA; Wattage: 1/10W; Weight: 0.8mg; Datasheet: Y:\MIS_DATABASE\DATASHEETS\RESISTORS\PAN-ERJSER_NOV17.PDF
R39 = RESISTOR: RES 5.76K 1/10W 1% 0402; Chkd/date: MAZHAR/150709; Crtd /date: USMAN/220808; Custom_Duty: 15%; Customs_HS_Code: 85332119; Distributor_name: DIGIKEY; Distributor_part_number: P5.76KLCT-ND; Footprint Path: Y:\MIS_DATABASE\Library\ALTIUM_TOOL\PCB_FOOTPRINTS\Altium_Footprint_Lib.PcbLib; Height: 0.40MM; Library Path: Y:\MIS_DATABASE\Library\ALTIUM_TOOL\SCHEMATICS_PARTS\MS_DISCRETE_Library.schlib; Mfr_name: PANASONIC-ECG; Mfr_part_number: ERJ-2RKF5761X; Mistral Part No: 110009030945-R; Package: 0402; Part_type: RESISTORS\FIXED; Project: CPB; RoHS: RoHS; Temperature: -55°C+155°C; Tolerance: 1%; Voltage: NA; Wattage: 1/10W; Weight: 0.8mg; Datasheet: Y:\MIS_DATABASE\DATASHEETS\RESISTORS\PAN-ERJSER_NOV17.PDF
R42 R79 = RESISTOR: RES 2.2K 1/16W 5% 0402; Chkd/date: VASANTHA/061216; Crtd /date: BAVISH/021210; Custom_Duty: 15%; Customs_HS_Code: 85332119; Distributor_name: DIGIKEY; Distributor_part_number: 311-2.2KJRCT-ND; Footprint Path: Y:\MIS_DATABASE\Library\ALTIUM_TOOL\PCB_FOOTPRINTS\Altium_Footprint_Lib.PcbLib; Height: 0.40MM; Library Path: Y:\MIS_DATABASE\Library\ALTIUM_TOOL\SCHEMATICS_PARTS\MS_DISCRETE_Library.schlib; Mfr_name: YAGEO AMERICA; Mfr_part_number: RC0402JR-072K2L; Mistral Part No: 110010120018-R; Package: 0402; Part_type: RESISTORS\FIXED; Project: TE4; RoHS: RoHS; Temperature: -55°C+155°C; Tolerance: 5%; Voltage: NA; Wattage: 1/16W; Weight: 0.65mg; Datasheet: Y:\MIS_DATABASE\DATASHEETS\RESISTORS\RCXXXXL-SER_MAR18.PDF
R81 R240-R242 R278 R292 = RESISTOR: RES 10K 1/16W 5% 0402; Chkd/date: VASANTHA/061216; Crtd /date: MAZHAR/230805; Custom_Duty: 15%; Customs_HS_Code: 85332119; Distributor_name: DIGIKEY; Distributor_part_number: 311-10KJRCT-ND; Footprint Path: Y:\MIS_DATABASE\Library\ALTIUM_TOOL\PCB_FOOTPRINTS\Altium_Footprint_Lib.PcbLib; Height: 0.40MM; Library Path: Y:\MIS_DATABASE\Library\ALTIUM_TOOL\SCHEMATICS_PARTS\MS_DISCRETE_Library.schlib; Mfr_name: YAGEO AMERICA; Mfr_part_number: RC0402JR-0710KL; Mistral Part No: 110011060021-R; Package: 0402; Part_type: RESISTORS\FIXED; Project: HSE; RoHS: RoHS; Temperature: -55°C+155°C; Tolerance: 5%; Voltage: NA; Wattage: 1/16W; Weight: 0.65mg; Datasheet: Y:\MIS_DATABASE\DATASHEETS\RESISTORS\RCXXXXL-SER_MAR18.PDF
R299 = RESISTOR: RES 1M 1/10W 5% 0603; Chkd/date: VASANTHA/060217; Crtd /date: USMAN/111207; Custom_Duty: 15%; Customs_HS_Code: 85332119; Distributor_name: DIGIKEY; Distributor_part_number: P1.0MGCT-ND; Footprint Path: Y:\MIS_DATABASE\Library\ALTIUM_TOOL\PCB_FOOTPRINTS\Altium_Footprint_Lib.PcbLib; Height: 0.55MM; Library Path: Y:\MIS_DATABASE\Library\ALTIUM_TOOL\SCHEMATICS_PARTS\MS_DISCRETE_Library.schlib; Mfr_name: PANASONIC-ECG; Mfr_part_number: ERJ-3GEYJ105V; Mistral Part No: 110009030413-R; Package: 0603; Part_type: RESISTORS\FIXED; Project: BSN; RoHS: RoHS; Temperature: -55°C+155°C; Tolerance: 5%; Voltage: NA; Wattage: 1/10W; Weight: 2mg; Datasheet: Y:\MIS_DATABASE\DATASHEETS\RESISTORS\PAN-ERJSER_NOV17.PDF
U15 = DP83867IRRGZ_VQFN48: IC HIGH IMMUNITY 10/100/1000 Mb/s ETHERNET PHY LAYER TRANSCEIVER VQFN48; Chkd/date: MANIRAJA/110817; Crtd /date: MANIRAJA/110817; Custom_Duty: 15%; Customs_HS_Code: 85423100; Distributor_name: DIGIKEY; Distributor_part_number: DP83867IRRGZT-ND; Height: 1.00MM; Mfr_name: TEXAS INSTRUMENTS; Mistral Part No: 143017080002-R; Package: VQFN48; Part_type: ICS\TELECOM\TRANSCEIVER; Project: TI_SVB_CONTROLLER CARD; RoHS: RoHS; Temperature: -40°C+85°C; Tolerance: NA; Voltage: NA; Wattage: NA; Weight: NA; Datasheet: Y:\MIS_DATABASE\DATASHEETS\ICS\DIGITAL\BUSTRANSCEIVER\DP83867I.PDF
U69 = SN74LVC1G08DBVRE4_SOT23-5: IC SINGLE 2-INPUT POSITIVE AND GATE SOT23-5; Chkd/date: SUHAS/221010; Crtd /date: USMAN/151008; Custom_Duty: 15%; Customs_HS_Code: 85423100; Distributor_name: DIGIKEY; Distributor_part_number: SN74LVC1G08DBVRE4-ND; Height: 1.45MM; Mfr_name: TEXAS INSTRUMENTS; Mistral Part No: 141009060026-R; Part_type: ICS\DIGITAL\GATES; Project: KHAN_MAIN; RoHS: Sb/ Br FREE; Temperature: -40°C+85°C; Datasheet: Y:\MIS_DATABASE\DATASHEETS\ICS\DIGITAL\GATES\SN74LVC1G08.PDF
U75 = TS3DDR3812RUAR_WQFN42: IC 12-CH 1:2 MUX/DEMUX SWITCH FOR DDR3 APPLICATION WQFN42; Chkd/date: MANIRAJA/250918; Crtd /date: ALVY/250918; Custom_Duty: 15%; Customs_HS_Code: 85423100; Distributor_name: DIGIKEY; Distributor_part_number: 296-28307-1-ND; Footprint Path: Y:\MIS_DATABASE\Library\ALTIUM_TOOL\PCB_FOOTPRINTS\Altium_Footprint_Lib.PcbLib; Height: 0.80MM; Library Path: Y:\MIS_DATABASE\Library\ALTIUM_TOOL\SCHEMATICS_PARTS\MS_COMBINATIONAL_Library.schlib; Mfr_name: TEXAS INSTRUMENTS; Mistral Part No: 141018090023-R; Package: WQFN42; Part_type: ICS\DIGITAL\COMBINATIONAL; Project: TI_J7ES_EVM_CP; RoHS: RoHS; Temperature: -40°C+85°C; Tolerance: NA; Voltage: NA; Wattage: NA; Weight: 54.8mg; Datasheet: Y:\MIS_DATABASE\DATASHEETS\ICS\DIGITAL\COMBINATIONAL\TS3DDR3812.PDF
U23 = AM64-SVB_BGA441: IC AM64 SoC MICROPROCESSOR BGA441; Chkd/date: MANIRAJA/020520; Crtd /date: ALVY/090420; Custom_Duty: 15%; Customs_HS_Code: 85423100; Distributor_name: NA; Distributor_part_number: NA; Footprint Path: Y:\MIS_DATABASE\Library\ALTIUM_TOOL\PCB_FOOTPRINTS\Altium_Footprint_Lib.PcbLib; Height: 2.57MM; Library Path: Y:\MIS_DATABASE\Library\ALTIUM_TOOL\SCHEMATICS_PARTS\MS_MICROPROCESSOR_Library.schlib; Mfr_name: TEXAS INSTRUMENTS; Mfr_part_number: AM6442ASFGGAALV; Mistral Part No: 141220040002; Package: BGA441; Part_type: ICS\DIGITAL\MICROPROCESSOR; Project: AM64x_SVB BRD; RoHS: NA; Temperature: NA; Tolerance: NA; Voltage: NA; Wattage: NA; Weight: NA; Datasheet: Y:\MIS_DATABASE\DATASHEETS\ICS\DIGITAL\MICROCONTROLLER\AM64-SoC_SVB.PDF

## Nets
DGND: C35.2 C36.2 C38.2 C39.2 C41.2 C43.2 C44.2 C51.2 C52.2 C74.2 C75.2 C79.2 C86.1 C87.2 C88.2 C91.2 C92.2 C93.2 C97.2 C98.1 C103.2 C119.2 C120.2 C121.2 C220.2 C231.1 C237.2 C238.2 C240.1 C249.2 C253.2 C258.2 C259.2 C260.2 C261.2 C263.2 C266.2 C273.1 C274.2 C275.2 C276.2 C278.2 C279.2 C281.2 C282.1 C284.2 C285.2 C287.2 C288.2 C289.2 C290.2 C291.2 C292.2 C294.2 C296.2 C298.2 C299.2 C300.2 C302.2 C303.2 C304.2 C307.2 C308.2 C309.2 C310.2 C311.2 C312.2 C314.2 C315.2 C317.2 C318.2 C319.2 C321.2 C322.2 C323.2 C324.2 C325.2 C326.2 C327.2 C328.2 C329.2 C330.2 C331.2 C332.2 C333.2 C334.2 C335.2 C336.2 C337.2 C338.2 C339.2 C340.2 C341.2 C342.2 C343.2 C344.2 C345.2 C346.2 C347.2 C348.2 C350.2 C351.2 C352.2 C353.2 C354.2 C355.2 C356.2 C357.2 C358.2 C359.2 C360.2 C361.2 C362.2 C363.2 C364.2 C365.2 C366.1 C367.2 C368.2 C370.2 C371.2 C372.2 C373.2 C374.2 C375.2 C376.2 C377.2 C378.2 C379.2 C380.2 C381.2 C382.2 C383.2 C387.2 C390.2 C391.2 C396.2 C398.2 C399.2 C400.2 C475.2 C482.2 C483.2 C484.2 C500.2 Q3.2(S) Q12.2(S) Q13.2(S) R31.2 R34.2 R36.2 R52.2 R54.2 R70.2 R240.2 R241.2 R249.2 R251.2 R292.2 R299.2 R315.2 TP54.1(TP) TP63.1(TP) U15.49(GND) U69.3(GND) U75.43(GND) ; also on sheet 5 6 7 8 9 10 11 12 13 14 15 16 17 18 19 20 21 22 23 24 25 26 27 28 29 30 39 40
VCC_3V3_SYS: C35.1 C44.1 C52.1 C220.1 C237.1 C260.1 C266.1 C275.1 C276.1 C281.1 C284.1 R32.1 R33.1 R35.1 R37.2 R39.2 R41.1 R42.2 R51.1 R56.1 R76.1 R79.2 R81.1 R234.2 R242.2 R278.1 U15.19(VDDIO) U15.30(VDDIO) U15.41(VDDIO) U69.5(VCC) U75.1(VCC) U75.17(VCC) U75.30(VCC) ; also on sheet 5 6 7 8 10 11 12 13 14 15 16 17 18 19 20 21 23 24 25 26 27 29 30 39 40
VCC_5V0: R314.1 ; also on sheet 6 17 18 20 25
VDD_1V0: C36.1 C39.1 C41.1 C51.1 C238.1 C253.1 C259.1 C263.1 C274.1 U15.6(VDD1P0) U15.24(VDD1P0) U15.31(VDD1P0) U15.42(VDD1P0) ; also on sheet 16
VDD_2V5: C38.1 C43.1 C249.1 C258.1 C261.1 U15.3(VDDA2P5) U15.9(VDDA2P5) ; also on sheet 16 39 40
VDD_CORE: C315.1 C318.1 C323.1 C324.1 C325.1 C329.1 C332.1 C334.1 C335.1 C336.1 C339.1 C345.1 C352.1 C354.1 C482.1 C483.1 C484.1 R78.1 R106.1 R298.1 TP55.1(TP) U23.J10(VDD_CORE) U23.J12(VDD_CORE) U23.K9(VDD_CORE) U23.K11(VDD_CORE) U23.L8(VDD_CORE) U23.L12(VDD_CORE) U23.M9(VDD_CORE) U23.M11(VDD_CORE) U23.N8(VDD_CORE) U23.N10(VDD_CORE) U23.P9(VDD_CORE) ; also on sheet 14 15 25
VDD_DDR4: C288.1 C290.1 C294.1 C302.1 C303.1 C307.1 C308.1 C310.1 C311.1 C314.1 C317.1 U23.F7(VDDS_DDR) U23.G6(VDDS_DDR) U23.H7(VDDS_DDR) U23.J6(VDDS_DDR) U23.J8(VDDS_DDR_C) U23.K7(VDDS_DDR) U23.L6(VDDS_DDR) ; also on sheet 14 16 22
VDD_DLL_MMC0: C365.1 C373.1 C377.1 FB17.2 U23.H14(VDD_DLL_MMC0)
VDD_MMC1: C119.1 C382.1 U23.H15(VDDA_3P3_SDIO) ; also on sheet 24
VDDA_1V8: C79.1 C338.1 C342.1 C346.1 C370.1 FB3.1 FB5.1 FB6.1 FB13.1 FB15.1 FB18.1 FB20.1 U23.G11(VDDA_TEMP0) U23.H13(VDDS_OSC) U23.L11(VDDA_TEMP1) ; also on sheet 14
VDDA_1V8_MCU: C103.1 C353.1 C387.1 FB5.2 U23.K12(VDDA_MCU)
VDDA_1V8_SERDES: C120.1 C121.1 C375.1 FB6.2 U23.R14(VDDA_1P8_SERDES0) ; also on sheet 5
VDDA_1V8_USB0: C380.1 C398.1 C399.1 FB20.2 U23.R15(VDDA_1P8_USB0)
VDDA_ADC: C363.1 C367.1 C368.1 FB18.2 U23.J13(VDDA_ADC) ; also on sheet 7
VDDA_CORE: FB4.1 FB16.1 FB17.1 R75.2 R78.2 U23.K13(VDD_MMC0)
VDDA_PLL0: C327.1 C340.1 C355.1 FB15.2 U23.N12(VDDA_PLL0)
VDDA_PLL1: C299.1 C300.1 C322.1 FB13.2 U23.H9(VDDA_PLL1)
VDDA_PLL2: C74.1 C75.1 C347.1 FB3.2 U23.J11(VDDA_PLL2)
VDDA_SYS_MON: R314.2 R315.1 R604.2 U23.K10(VMON_VSYS)
VDDAR_0P85_SERDES0: C88.1 C91.1 C92.1 C93.1 C344.1 C356.1 C362.1 FB4.2 U23.P11(VDDA_0P85_SERDES0_C) U23.P12(VDDA_0P85_SERDES0) U23.P13(VDDA_0P85_SERDES0)
VDDAR_0P85_USB0: C341.1 C350.1 C358.1 FB16.2 U23.T12(VDDA_0P85_USB0)
VDDAR_CORE: R75.1 R297.1 ; also on sheet 14 15
VDDR_CORE: C86.2 C87.1 C330.1 C475.1 R106.2 R297.2 R307.1 TP61.1(TP) U23.L10(VDDR_CORE) U23.M13(VDDR_CORE) ; also on sheet 25
VDDSHV_SD_IO: C372.1 C381.1 C400.1 U23.K15(CAP_VDDSHV_MMC1) U23.L14(VDDSHV5) U23.L15(VDDSHV5) ; also on sheet 24
CAP_VDDS0: C390.1 U23.H12(CAP_VDDS0)
CAP_VDDS1: C298.1 U23.T7(CAP_VDDS1)
CAP_VDDS2: C348.1 U23.R11(CAP_VDDS2)
CAP_VDDS3: C357.1 U23.N14(CAP_VDDS3)
CAP_VDDS4: C396.1 U23.M16(CAP_VDDS4)
CAP_VDDS5: C391.1 U23.L13(CAP_VDDS5)
CAP_VDDS_MCU: C289.1 U23.H10(CAP_VDDS_MCU)
CPSW_EARTH: C287.1 J14.SH1 J14.SH2 R299.1
CPSW_ETH1_D0M: J14.10 U15.2(TD_M_A)
CPSW_ETH1_D0P: J14.11 U15.1(TD_P_A)
CPSW_ETH1_D1M: J14.5 U15.5(TD_M_B)
CPSW_ETH1_D1P: J14.4 U15.4(TD_P_B)
CPSW_ETH1_D2M: J14.2 U15.8(TD_M_C)
CPSW_ETH1_D2P: J14.3 U15.7(TD_P_C)
CPSW_ETH1_D3M: J14.9 U15.11(TD_M_D)
CPSW_ETH1_D3P: J14.8 U15.10(TD_P_D)
CPSW_ETH1_GPIO_0: R41.2 R230.2 R251.1 U15.39(GPIO_0)
CPSW_ETH1_GPIO_1: R35.2 R36.1 U15.40(GPIO_1)
CPSW_ETH1_LED0: TP9.1(TP) U15.47(LED_0)
CPSW_ETH1_LED1: J14.13 Q13.3(D)
CPSW_ETH1_LED2: J14.16 Q12.3(D) R234.1
CPSW_ETH1_LED3: J14.15 Q3.3(D) R37.1
CPSW_ETH1_LED_1000: R30.2 R31.1 R32.2 U15.46(LED_1)
CPSW_ETH1_LED_ACT: R33.2 R34.1 R286.1 U15.45(LED_2)
CPSW_FET_EN: R278.2 U75.8(EN)
CPSW_FET_SEL: R292.1 U75.9(SEL1) U75.10(SEL2) ; also on sheet 13
CPSW_RGMII1_ETH1_CLK: C501.1 ; also on sheet 11
CPSW_RGMII1_ETH1_CLK_OUT: TP16.1(TP) U15.18(CLK_OUT)
CPSW_RGMII1_ETH1_RBIAS: R70.1 U15.12(RBIAS)
CPSW_RGMII1_MDC: R81.2 U15.16(MDC) ; also on sheet 18 39
CPSW_RGMII1_MDIO: R79.1 U15.17(MDIO) ; also on sheet 18 39
CPSW_RGMII1_RD0: R54.1 R56.2 U15.33(RX_D0) U75.41(B0)
CPSW_RGMII1_RD1: U15.34(RX_D1) U75.39(B1)
CPSW_RGMII1_RD2: R51.2 R52.1 U15.35(RX_D2) U75.38(B2)
CPSW_RGMII1_RD3: U15.36(RX_D3) U75.36(B3)
CPSW_RGMII1_RESETn: R240.1 U15.43(RESET_N) U69.4(Y)
CPSW_RGMII1_RX_CTL: R39.1 R249.1 U15.38(RX_DV/RX_CTRL) U75.34(B4)
CPSW_RGMII1_RXC: U15.32(RX_CLK) U75.32(B5)
CPSW_RGMII1_TD0: U15.28(TX_D0) ; also on sheet 18
CPSW_RGMII1_TD1: U15.27(TX_D1) ; also on sheet 18
CPSW_RGMII1_TD2: U15.26(TX_D2) ; also on sheet 18
CPSW_RGMII1_TD3: U15.25(TX_D3) ; also on sheet 18
CPSW_RGMII1_TX_CTL: U15.37(TX_EN/TX_CTRL) ; also on sheet 18
CPSW_RGMII1_TXC: U15.29(GTX_CLK) ; also on sheet 18
CPSW_RGMII_INTn: R42.1 R250.2 U15.44(INT/PWDN)
GPIO_CPSW1_RST: R241.1 R242.1 U69.1(A) ; also on sheet 13
HSE_PRG0_PRU0_GPO9: U75.33(C4) ; also on sheet 18
HSE_PRG0_PRU0_GPO10: U75.31(C5) ; also on sheet 18
HSE_PRG0_PRU1_GPO7: U75.42(C0) ; also on sheet 18
HSE_PRG0_PRU1_GPO9: U75.40(C1) ; also on sheet 18
HSE_PRG0_PRU1_GPO10: U75.37(C2) ; also on sheet 18
HSE_PRG0_PRU1_GPO17: U75.35(C3) ; also on sheet 18
PORz_OUT: U69.2(B) ; also on sheet 12 24 29 39 40
PRG0_PRU0_GPO9/CPSW_RGMII1_RX_CTL: U75.6(A4) ; also on sheet 18
PRG0_PRU0_GPO10/CPSW_RGMII1_RXC: U75.7(A5) ; also on sheet 18
PRG0_PRU1_GPO7/CPSW_RGMII1_RD0: U75.2(A0) ; also on sheet 18
PRG0_PRU1_GPO9/CPSW_RGMII1_RD1: U75.3(A1) ; also on sheet 18
PRG0_PRU1_GPO10/CPSW_RGMII1_RD2: U75.4(A2) ; also on sheet 18
PRG0_PRU1_GPO17/CPSW_RGMII1_RD3: U75.5(A3) ; also on sheet 18
PRG1_RGMII_INTn: R250.1 ; also on sheet 12 39 40
SOC_DVDD1V8: C97.1 C98.2 C359.1 C371.1 C379.1 C383.1 U23.E12(VMON_1P8_SOC) U23.J15(VDDS_MMC0) U23.K14(VDDS_MMC0) U23.K16(VMON_1P8_MCU) U23.M14(VDDSHV4) U23.M15(VDDSHV4) ; also on sheet 14
SoC_DVDD3V3: C304.1 C309.1 C312.1 C319.1 C321.1 C326.1 C328.1 C331.1 C333.1 C337.1 C343.1 C351.1 C360.1 C361.1 C364.1 C366.2 C374.1 C376.1 C378.1 U23.F9(VDDSHV_MCU) U23.F11(VDDSHV0) U23.F13(VMON_3P3_MCU) U23.F14(VMON_3P3_SOC) U23.G8(VDDSHV_MCU) U23.G10(VDDSHV_MCU) U23.G12(VDDSHV0) U23.G14(VDDSHV0) U23.M7(VDDSHV1) U23.N6(VDDSHV1) U23.P7(VDDSHV1) U23.P14(VDDSHV3) U23.P15(VDDSHV3) U23.R8(VDDSHV2) U23.R10(VDDSHV2) U23.R13(VDDA_3P3_USB0) U23.T9(VDDSHV2) ; also on sheet 14
TEMP_DIODE_P: TP75.1(TP) U23.F12(TEMP_DIODE_P)
VMAIN: R604.1 ; also on sheet 5 8 16 17
VPP_1V8: U23.G15(VPP) ; also on sheet 15
N5126260: TP11.1(TP) U15.13(VDDA1P8) U15.48(VDDA1P8)
N18116794: Q13.1(G) R286.2
N18116818: Q12.1(G) R230.1
N18116875: Q3.1(G) R30.1
N26314477: C278.1 C279.1 C285.1 R298.2
N26314562: C291.1 C292.1 C296.1 R307.2
N27215594: J14.14 R76.2
N27215846: C231.2 J14.12
N27215858: C240.2 J14.6
N27215870: C273.2 J14.1
N27215882: C282.2 J14.7
N28787498: C500.1 C501.2 U15.15(XI)

Not connected (* = marked no-connect by the designer): U15 14(XO)* 20(JTAG_CLK)* 21(JTAG_TDO)* 22(JTAG_TMS)* 23(JTAG_TDI)*; U75 11(A6)* 12(A7)* 13(A8)* 14(A9)* 15(A10)* 16(A11)* 18(C11)* 19(B11)* 20(C10)* 21(B10)* 22(C9)* 23(B9)* 24(C8)* 25(B8)* 26(C7)* 27(B7)* 28(C6)* 29(B6)*

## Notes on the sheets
sheet 1
- BLOCK DIAGRAM_XDS110
sheet 2
- Decaps
- CPSW RGMII 1 -  PHY
- RJ45 with Integrated Mangnetics
- CAP DIVIDER CIRCUIT
  ADDED SINCE THE CLOCK
  SOURCE IS 3.3V
- STRAPPING RESISTORS
- CPSW ETH1 RESET
- CPSW_ETHERNET PHY- 1 SPEED & ACTIVITY  LED 's DRIVERS
- PHY ADDRESS = 00000
- Auto-negotiation Enabled
- 10/100/1000 advertised, Auto-MDI-X
- Tx & Rx Clock Skew = 2.0ns
- CPSW RGMII 1 ETHERNET PHY SIGNALS & HSE CON SIGNALS
- Off Page Connections
- From
  Processor
- TS3DDR3812RUAR Truth Table
- From Processor
- EN
- SEL1
- SEL2
- FUNCTION
- L
- X
- X
- A0 to A11, B0 to B11, and C0 to C11 are Hi-Z
- H
- L
- L
- A0 to A5 = B0 to B5 and A6 to A11 = B6 to B11
- H
- L
- H
- A0 to A5 = B0 to B5 and A6 to A11 = C6 to C11
- From IO Expander
- H
- H
- L
- A0 to A5 = C0 to C5 and A6 to A11 = B6 to B11
- From Clock Buffer
- H
- H
- H
- A0 to A5 = C0 to C5 and A6 to A11 = C6 to C11
- To HSE Connector
- From Processor
sheet 3
- SoC POWER Decaps
- Place one 0.1uF cap near each Pin
- To place after current sense
  resitor on VDD_CORE plane
- Place one 0.1uF cap near each Pin
- VDD ARRAY CORE
- VDDA_3P3_SDIO
- Place one 0.1uF cap near each Pin
- Place one 0.1uF cap near each Pin
- Core & Array Core Supply Kelvin Sensing
sheet 4
- SoC POWER
- R3
- R4
- 1.8V Analog SUPPLY
- R1
- R2
- 1.8V Analog SUPPLY
- CORE SUPPLY
- ARRAY CORE SUPPLY
- STEERING RESISTORS
- 0.75 VDD_CORE
- 0.85 VDDR_CORE&OTHERS
- R2 & R4 INSTALLED
- 0.8 VDD_CORE
- 0.85 VDDR_CORE&OTHERS
- R2 & R4 INSTALLED
- 0.8 VDD_CORE & OTHERS
- 0.85 VDDR_CORE
- R1 & R4 INSTALLED
- 0.85 VDD_CORE,VDDR_CORE&OTHERS
- NONE
- R1 & R3 INSTALLED
- CORE SUPPLY
